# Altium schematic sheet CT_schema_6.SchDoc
size 278 x 170 mm
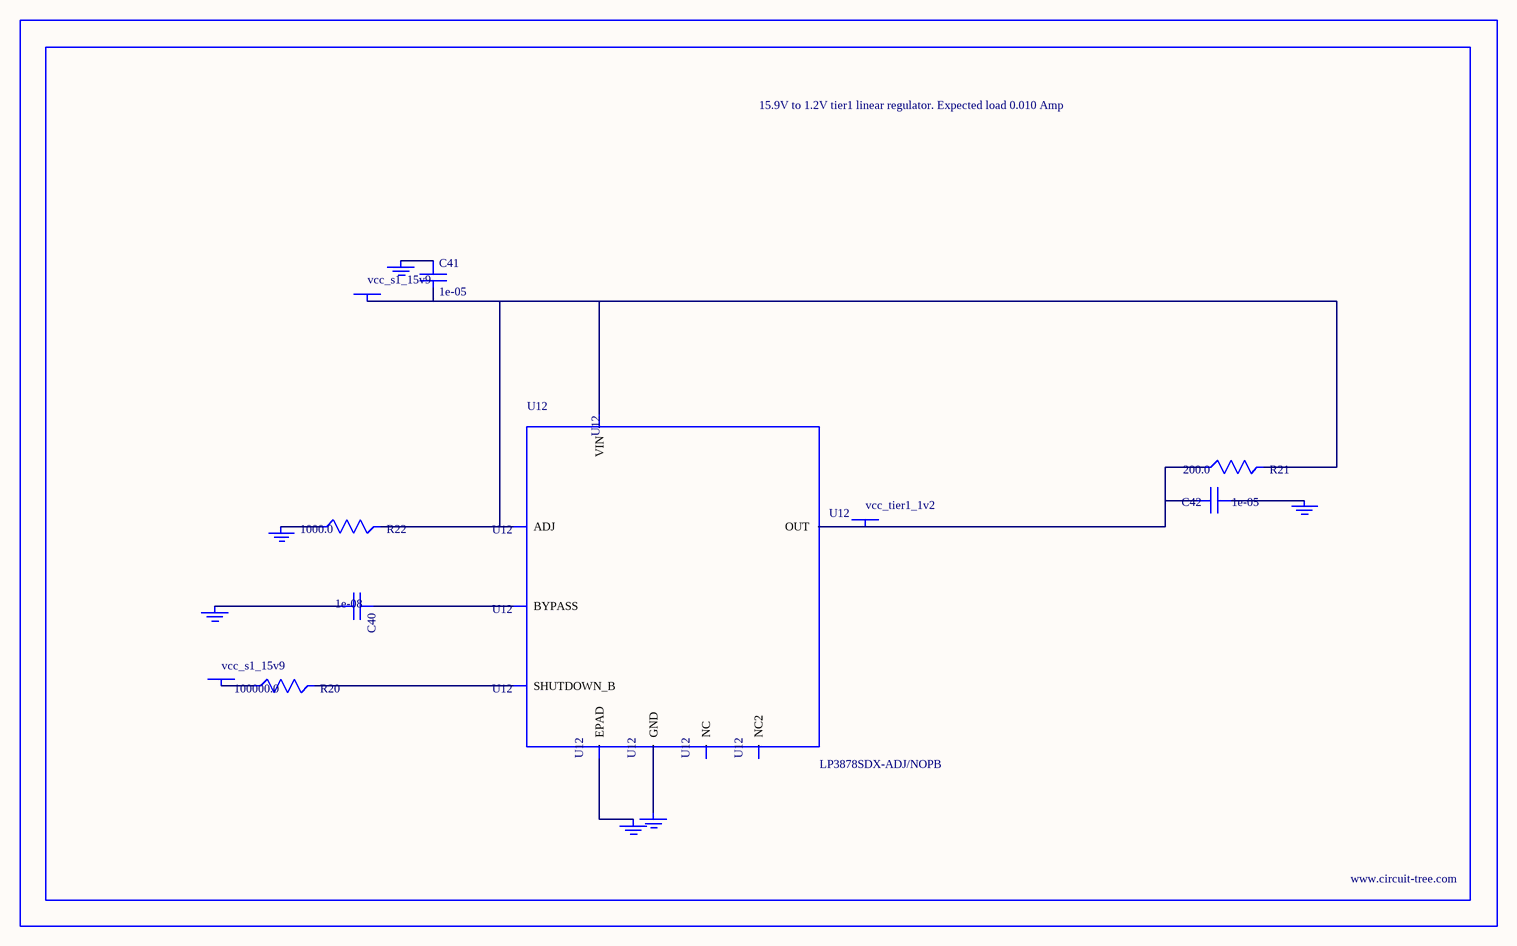
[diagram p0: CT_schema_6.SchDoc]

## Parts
BORDER5  (no value)
C40  1e-08  [C0402]
C41  1e-05  [C1210]
C42  1e-05  [C0805]
GND_INSTANCE_5_0  (no value)
GND_INSTANCE_5_1  (no value)
GND_INSTANCE_5_2  (no value)
GND_INSTANCE_5_3  (no value)
GND_INSTANCE_5_4  (no value)
GND_INSTANCE_5_5  (no value)
POWER_INSTANCE_5_0  vcc_s1_15v9
POWER_INSTANCE_5_1  vcc_s1_15v9
POWER_INSTANCE_5_2  vcc_tier1_1v2
R20  100000.0  [R0603]
R21  200.0  [R0603]
R22  1000.0  [R0603]
U12  LP3878SDX-ADJ/NOPB  [WSON-8]

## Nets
NetC40_1: C40.1 U12.1(BYPASS)
NetC40_2: C40.2 GND_INSTANCE_5_0.0(GND)
NetC41_1: C41.1 GND_INSTANCE_5_1.0(GND)
NetC41_2: C41.2 POWER_INSTANCE_5_0.0(PWR) R21.2 R22.2 U12.4(VIN) U12.6(ADJ)
NetC42_1: C42.1 GND_INSTANCE_5_2.0(GND)
NetC42_2: C42.2 POWER_INSTANCE_5_2.0(PWR) R21.1 U12.5(OUT)
NetGND_INSTANCE_5_3_0: GND_INSTANCE_5_3.0(GND) R22.1
NetGND_INSTANCE_5_4_0: GND_INSTANCE_5_4.0(GND) U12.PAD(EPAD)
NetGND_INSTANCE_5_5_0: GND_INSTANCE_5_5.0(GND) U12.3(GND)
NetPOWER_INSTANCE_5_1_0: POWER_INSTANCE_5_1.0(PWR) R20.1
NetR20_2: R20.2 U12.8(SHUTDOWN_B)

Not connected (* = marked no-connect by the designer): U12 2(NC) 7(NC2)

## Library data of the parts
BORDER5 = BORDER_PAGE5
C40 = C0402C103K3RAC
C41 = C1210C106K5PACTU
C42 = GRM219R60J106ME19D
GND_INSTANCE_5_0-GND_INSTANCE_5_5 = GND
POWER_INSTANCE_5_0-POWER_INSTANCE_5_2 = PWR
R20 = RC0603JR-07100KL
R21 = RC0603JR-07200RL
R22 = RC0603JR-071KL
